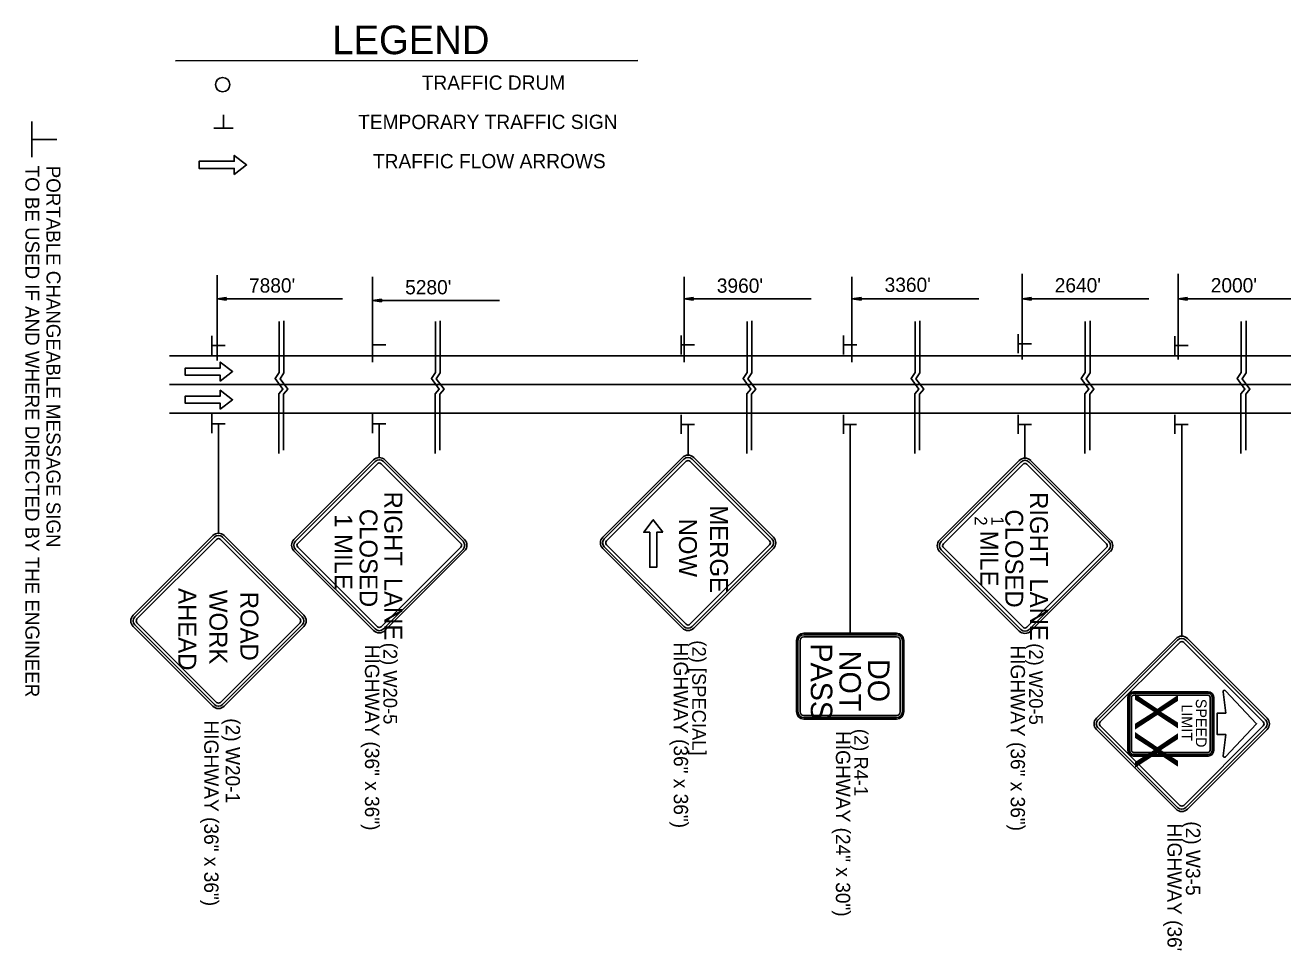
# Model space of a CAD drawing. Extents: x 1930579 to 1937521, y 596183 to 597566.
# Drawn here: x 1935128 to 1935656, y 596916 to 597301 of the extents above; entities that cross this region are included whole.
import ezdxf

# ---------------------------------------------------------------- set-up
doc = ezdxf.new("R2010")
doc.units = 0
for name, color, linetype in [('Default', 7, 'Continuous'), ('P_TC_Signs_Permanent', 7, 'Continuous'), ('P_TC_Signs_Temporary', 7, 'Continuous'), ('R_Annotation', 7, 'Continuous'), ('R_MOT', 7, 'Continuous'), ('R_Striping', 7, 'Continuous')]:
    doc.layers.add(name, color=color, linetype=linetype)

msp = doc.modelspace()

# ---------------------------------------------------------------- linework, layer by layer
at = {"layer": 'Default'}
for p, q in [((1935130.71, 597245.94), (1935130.71, 597260.96)), ((1935130.93, 597253.41), (1935141.18, 597253.41)), ((1935208.44, 597196.5), (1935208.44, 597160.58)), ((1935546.1, 597197.04), (1935546.1, 597161.13)), ((1935611.55, 597197.04), (1935611.55, 597161.13)), ((1935273.63, 597195.82), (1935273.63, 597159.91)), ((1935404.36, 597195.82), (1935404.36, 597159.91)), ((1935474.74, 597195.82), (1935474.74, 597159.91)), ((1935212.26, 597187.09), (1935208.44, 597186.51)), ((1935208.44, 597186.51), (1935261.07, 597186.51)), ((1935212.26, 597185.94), (1935208.44, 597186.51)), ((1935212.26, 597186.99), (1935209.08, 597186.51)), ((1935212.26, 597186.03), (1935209.08, 597186.51)), ((1935212.26, 597186.89), (1935209.73, 597186.51)), ((1935212.26, 597186.13), (1935209.73, 597186.51)), ((1935212.26, 597186.8), (1935210.37, 597186.51)), ((1935212.26, 597186.23), (1935210.37, 597186.51)), ((1935212.26, 597186.7), (1935211.02, 597186.51)), ((1935212.26, 597186.33), (1935211.02, 597186.51)), ((1935212.26, 597186.6), (1935211.66, 597186.51)), ((1935212.26, 597186.42), (1935211.66, 597186.51)), ((1935212.26, 597185.94), (1935212.26, 597187.09)), ((1935277.46, 597186.41), (1935273.63, 597185.83)), ((1935273.63, 597185.83), (1935326.86, 597185.83)), ((1935277.46, 597185.26), (1935273.63, 597185.83)), ((1935277.46, 597186.31), (1935274.27, 597185.83)), ((1935277.46, 597185.35), (1935274.27, 597185.83)), ((1935277.46, 597186.21), (1935274.93, 597185.83)), ((1935277.46, 597185.45), (1935274.93, 597185.83)), ((1935277.46, 597186.12), (1935275.57, 597185.83)), ((1935277.46, 597185.55), (1935275.57, 597185.83)), ((1935277.46, 597186.02), (1935276.21, 597185.83)), ((1935277.46, 597185.65), (1935276.21, 597185.83)), ((1935277.46, 597185.92), (1935276.85, 597185.83)), ((1935277.46, 597185.74), (1935276.85, 597185.83)), ((1935277.46, 597185.26), (1935277.46, 597186.41)), ((1935408.18, 597187.09), (1935404.36, 597186.51)), ((1935404.36, 597186.51), (1935457.59, 597186.51)), ((1935408.18, 597185.94), (1935404.36, 597186.51)), ((1935408.18, 597186.99), (1935405, 597186.51)), ((1935408.18, 597186.03), (1935405, 597186.51)), ((1935408.18, 597186.89), (1935405.65, 597186.51)), ((1935408.18, 597186.13), (1935405.65, 597186.51)), ((1935408.18, 597186.8), (1935406.29, 597186.51)), ((1935408.18, 597186.23), (1935406.29, 597186.51)), ((1935408.18, 597186.7), (1935406.94, 597186.51)), ((1935408.18, 597186.33), (1935406.94, 597186.51)), ((1935408.18, 597186.6), (1935407.58, 597186.51)), ((1935408.18, 597186.42), (1935407.58, 597186.51)), ((1935408.18, 597185.94), (1935408.18, 597187.09)), ((1935478.57, 597187.09), (1935474.74, 597186.51)), ((1935474.74, 597186.51), (1935527.97, 597186.51)), ((1935478.57, 597185.94), (1935474.74, 597186.51)), ((1935478.57, 597186.99), (1935475.38, 597186.51)), ((1935478.57, 597186.03), (1935475.38, 597186.51)), ((1935478.57, 597186.89), (1935476.04, 597186.51)), ((1935478.57, 597186.13), (1935476.04, 597186.51)), ((1935478.57, 597186.8), (1935476.67, 597186.51)), ((1935478.57, 597186.23), (1935476.67, 597186.51)), ((1935478.57, 597186.7), (1935477.32, 597186.51)), ((1935478.57, 597186.33), (1935477.32, 597186.51)), ((1935478.57, 597186.6), (1935477.96, 597186.51)), ((1935478.57, 597186.42), (1935477.96, 597186.51)), ((1935478.57, 597185.94), (1935478.57, 597187.09)), ((1935549.93, 597187.09), (1935546.1, 597186.51)), ((1935546.1, 597186.51), (1935599.33, 597186.51)), ((1935549.93, 597185.94), (1935546.1, 597186.51)), ((1935549.93, 597186.99), (1935546.74, 597186.51)), ((1935549.93, 597186.03), (1935546.74, 597186.51)), ((1935549.93, 597186.89), (1935547.4, 597186.51)), ((1935549.93, 597186.13), (1935547.4, 597186.51)), ((1935549.93, 597186.8), (1935548.04, 597186.51)), ((1935549.93, 597186.23), (1935548.04, 597186.51)), ((1935549.93, 597186.7), (1935548.69, 597186.51)), ((1935549.93, 597186.33), (1935548.69, 597186.51)), ((1935549.93, 597186.6), (1935549.32, 597186.51)), ((1935549.93, 597186.42), (1935549.32, 597186.51)), ((1935549.93, 597185.94), (1935549.93, 597187.09)), ((1935615.37, 597187.09), (1935611.55, 597186.51)), ((1935611.55, 597186.51), (1935664.78, 597186.51)), ((1935615.37, 597185.94), (1935611.55, 597186.51)), ((1935615.37, 597186.99), (1935612.18, 597186.51)), ((1935615.37, 597186.03), (1935612.18, 597186.51)), ((1935615.37, 597186.89), (1935612.84, 597186.51)), ((1935615.37, 597186.13), (1935612.84, 597186.51)), ((1935615.37, 597186.8), (1935613.48, 597186.51)), ((1935615.37, 597186.23), (1935613.48, 597186.51)), ((1935615.37, 597186.7), (1935614.13, 597186.51)), ((1935615.37, 597186.33), (1935614.13, 597186.51)), ((1935615.37, 597186.6), (1935614.77, 597186.51)), ((1935615.37, 597186.42), (1935614.77, 597186.51)), ((1935615.37, 597185.94), (1935615.37, 597187.09)), ((1935206.22, 597170.98), (1935206.22, 597163)), ((1935273.63, 597171.15), (1935273.63, 597163.17)), ((1935403.18, 597171.2), (1935403.18, 597163.22)), ((1935471.18, 597171.13), (1935471.18, 597163.15)), ((1935544.49, 597171.65), (1935544.49, 597163.68)), ((1935610.26, 597170.87), (1935610.26, 597162.89)), ((1935206.34, 597167.01), (1935211.78, 597167.01)), ((1935273.75, 597167.18), (1935279.2, 597167.18)), ((1935403.3, 597167.23), (1935408.75, 597167.23)), ((1935471.3, 597167.16), (1935476.75, 597167.16)), ((1935544.6, 597167.69), (1935550.05, 597167.69)), ((1935610.37, 597166.9), (1935615.82, 597166.9)), ((1936503.04, 597162.55), (1935188.53, 597162.55)), ((1936503.04, 597150.55), (1935188.53, 597150.55)), ((1936503.04, 597138.55), (1935188.53, 597138.55)), ((1935361.56, 597138.55), (1935431.95, 597138.55)), ((1935206.22, 597130.11), (1935206.22, 597138.09)), ((1935206.34, 597134.07), (1935211.78, 597134.07)), ((1935273.65, 597130.11), (1935273.65, 597138.09)), ((1935273.77, 597134.07), (1935279.21, 597134.07)), ((1935403.18, 597129.89), (1935403.18, 597137.87)), ((1935403.3, 597133.86), (1935408.75, 597133.86)), ((1935471.17, 597129.89), (1935471.17, 597137.87)), ((1935471.29, 597133.86), (1935476.73, 597133.86)), ((1935544.5, 597129.89), (1935544.5, 597137.87)), ((1935544.61, 597133.86), (1935550.06, 597133.86)), ((1935610.26, 597129.89), (1935610.26, 597137.87)), ((1935610.38, 597133.86), (1935615.83, 597133.86))]:
    msp.add_line(p, q, dxfattribs=at)
for points in [[(1935234.46, 597177.07), (1935234.46, 597155.55), (1935232.8, 597153.08), (1935236.04, 597148.65), (1935234.33, 597146.6), (1935234.33, 597121.58)], [(1935236.51, 597177.27), (1935236.51, 597155.46), (1935234.85, 597152.99), (1935238.08, 597148.56), (1935236.38, 597146.52), (1935236.38, 597123.02)], [(1935300.04, 597177.07), (1935300.04, 597155.55), (1935298.38, 597153.08), (1935301.62, 597148.65), (1935299.91, 597146.6), (1935299.91, 597121.58)], [(1935302.08, 597177.27), (1935302.08, 597155.46), (1935300.42, 597152.99), (1935303.66, 597148.56), (1935301.96, 597146.52), (1935301.95, 597123.02)], [(1935430.77, 597177.07), (1935430.77, 597155.55), (1935429.1, 597153.08), (1935432.34, 597148.65), (1935430.64, 597146.6), (1935430.63, 597121.58)], [(1935432.81, 597177.27), (1935432.81, 597155.46), (1935431.15, 597152.99), (1935434.39, 597148.56), (1935432.68, 597146.52), (1935432.68, 597123.02)], [(1935501.24, 597177.07), (1935501.24, 597155.55), (1935499.58, 597153.08), (1935502.81, 597148.65), (1935501.11, 597146.6), (1935501.1, 597121.58)], [(1935503.28, 597177.27), (1935503.28, 597155.46), (1935501.62, 597152.99), (1935504.86, 597148.56), (1935503.15, 597146.52), (1935503.15, 597123.02)], [(1935572.6, 597177.07), (1935572.6, 597155.55), (1935570.94, 597153.08), (1935574.18, 597148.65), (1935572.47, 597146.6), (1935572.47, 597121.58)], [(1935574.64, 597177.27), (1935574.64, 597155.46), (1935572.98, 597152.99), (1935576.22, 597148.56), (1935574.52, 597146.52), (1935574.51, 597123.02)], [(1935638.04, 597177.07), (1935638.04, 597155.55), (1935636.38, 597153.08), (1935639.62, 597148.65), (1935637.92, 597146.6), (1935637.91, 597121.58)], [(1935640.09, 597177.27), (1935640.09, 597155.46), (1935638.43, 597152.99), (1935641.66, 597148.56), (1935639.96, 597146.52), (1935639.96, 597123.02)]]:
    msp.add_lwpolyline(points, dxfattribs=at)
msp.add_circle((1935210.78, 597276.42), 3, dxfattribs=at)
at = {"layer": 'P_TC_Signs_Permanent'}
for p, q in [((1935493.51, 597046.19), (1935454.51, 597046.19)), ((1935493.51, 597045.59), (1935454.51, 597045.59)), ((1935493.51, 597044.69), (1935454.51, 597044.69)), ((1935610.72, 597043.97), (1935577.31, 597010.55)), ((1935648.9, 597010.55), (1935615.49, 597043.97)), ((1935451.51, 597043.19), (1935451.51, 597013.19)), ((1935452.11, 597043.19), (1935452.11, 597013.19)), ((1935453.01, 597043.19), (1935453.01, 597013.19)), ((1935495.01, 597013.19), (1935495.01, 597043.19)), ((1935495.91, 597013.19), (1935495.91, 597043.19)), ((1935496.51, 597013.19), (1935496.51, 597043.19)), ((1935611.38, 597043.3), (1935577.97, 597009.89)), ((1935612.31, 597042.37), (1935578.9, 597008.96)), ((1935647.31, 597008.96), (1935613.9, 597042.37)), ((1935648.24, 597009.89), (1935614.83, 597043.3)), ((1935590.51, 596997.07), (1935590.51, 597019.27)), ((1935592.91, 597021.67), (1935624.11, 597021.67)), ((1935626.51, 597019.27), (1935626.51, 596997.07)), ((1935454.51, 597011.69), (1935493.51, 597011.69)), ((1935454.51, 597010.79), (1935493.51, 597010.79)), ((1935454.51, 597010.19), (1935493.51, 597010.19)), ((1935577.97, 597006.44), (1935611.38, 596973.03)), ((1935578.9, 597007.37), (1935612.31, 596973.96)), ((1935613.9, 596973.96), (1935647.31, 597007.37)), ((1935614.83, 596973.03), (1935648.24, 597006.44)), ((1935577.31, 597005.78), (1935610.72, 596972.37)), ((1935615.49, 596972.37), (1935648.9, 597005.78)), ((1935624.11, 596994.67), (1935592.91, 596994.67))]:
    msp.add_line(p, q, dxfattribs=at)
for points in [[(1935591.11, 597019.27), (1935591.11, 596997.07)], [(1935592.01, 596997.07), (1935592.01, 597019.27)], [(1935624.11, 597021.07), (1935592.91, 597021.07)], [(1935592.91, 597020.17), (1935624.11, 597020.17)], [(1935625.01, 597019.27), (1935625.01, 597008.17), (1935625.01, 596997.07)], [(1935625.91, 596997.07), (1935625.91, 597008.17), (1935625.91, 597019.27)], [(1935630.46, 597021.63), (1935631.58, 597012.67), (1935628.01, 597012.67), (1935628.01, 597003.67), (1935631.57, 597003.67), (1935630.46, 596994.78)], [(1935631.42, 596994.32), (1935644.51, 597008.2), (1935631.42, 597022.08)], [(1935624.11, 596996.17), (1935592.91, 596996.17)], [(1935592.91, 596995.27), (1935624.11, 596995.27)]]:
    msp.add_lwpolyline(points, dxfattribs=at)
for centre, radius, start, end in [((1935454.51, 597043.19), 3, 90, 180), ((1935454.51, 597043.19), 2.4, 90, 180), ((1935454.51, 597043.19), 1.5, 90, 180), ((1935493.51, 597043.19), 3, 360, 90), ((1935493.51, 597043.19), 2.4, 360, 90), ((1935493.51, 597043.19), 1.5, 360, 90), ((1935613.1, 597041.58), 3.38, 45, 135), ((1935613.1, 597041.58), 2.44, 45, 135), ((1935613.1, 597041.58), 1.13, 45, 135), ((1935631.02, 597021.7), 0.563, 43.3117, 187.125), ((1935592.91, 597019.27), 2.4, 90, 180), ((1935592.91, 597019.27), 1.8, 90, 180), ((1935592.91, 597019.27), 0.9, 90, 180), ((1935624.11, 597019.27), 2.4, 0, 90), ((1935624.11, 597019.27), 1.8, 0, 90), ((1935624.11, 597019.27), 0.9, 0, 90), ((1935454.51, 597013.19), 3, 180, 270), ((1935454.51, 597013.19), 2.4, 180, 270), ((1935454.51, 597013.19), 1.5, 180, 270), ((1935493.51, 597013.19), 3, 270, 360), ((1935493.51, 597013.19), 2.4, 270, 360), ((1935493.51, 597013.19), 1.5, 270, 360), ((1935579.69, 597008.17), 3.38, 135, 225), ((1935579.69, 597008.17), 2.44, 135, 225), ((1935579.69, 597008.17), 1.13, 135, 225), ((1935646.51, 597008.17), 1.13, 315, 45), ((1935646.51, 597008.17), 2.44, 315, 45), ((1935646.51, 597008.17), 3.38, 315, 45), ((1935592.91, 596997.07), 2.4, 180, 270), ((1935592.91, 596997.07), 1.8, 180, 270), ((1935592.91, 596997.07), 0.9, 180, 270), ((1935624.11, 596997.07), 2.4, 270, 0), ((1935624.11, 596997.07), 1.8, 270, 0), ((1935624.11, 596997.07), 0.9, 270, 0), ((1935631.02, 596994.71), 0.563, 172.875, 316.6883), ((1935613.1, 596974.76), 3.38, 225, 315), ((1935613.1, 596974.76), 2.44, 225, 315), ((1935613.1, 596974.76), 1.13, 225, 315)]:
    msp.add_arc(centre, radius, start, end, dxfattribs=at)
at = {"layer": 'P_TC_Signs_Temporary'}
for p, q in [((1935240.69, 597085.51), (1935274.1, 597118.92)), ((1935241.36, 597084.85), (1935274.77, 597118.26)), ((1935242.29, 597083.92), (1935275.7, 597117.33)), ((1935277.29, 597117.33), (1935310.7, 597083.92)), ((1935278.21, 597118.26), (1935311.63, 597084.85)), ((1935278.88, 597118.92), (1935312.29, 597085.51)), ((1935370.23, 597086.53), (1935403.64, 597119.94)), ((1935370.89, 597085.87), (1935404.3, 597119.28)), ((1935371.82, 597084.94), (1935405.23, 597118.35)), ((1935406.82, 597118.35), (1935440.23, 597084.94)), ((1935407.75, 597119.28), (1935441.16, 597085.87)), ((1935408.41, 597119.94), (1935441.82, 597086.53)), ((1935511.54, 597085.29), (1935544.95, 597118.71)), ((1935512.2, 597084.63), (1935545.61, 597118.04)), ((1935549.06, 597118.04), (1935582.47, 597084.63)), ((1935549.72, 597118.71), (1935583.13, 597085.29)), ((1935513.13, 597083.7), (1935546.54, 597117.11)), ((1935548.13, 597117.11), (1935581.54, 597083.7)), ((1935173.26, 597053.77), (1935206.67, 597087.18)), ((1935173.93, 597053.11), (1935207.34, 597086.52)), ((1935174.85, 597052.18), (1935208.26, 597085.59)), ((1935209.86, 597085.59), (1935243.27, 597052.18)), ((1935210.78, 597086.52), (1935244.19, 597053.11)), ((1935211.45, 597087.18), (1935244.86, 597053.77)), ((1935274.1, 597047.33), (1935240.69, 597080.74)), ((1935274.77, 597047.99), (1935241.36, 597081.4)), ((1935275.7, 597048.92), (1935242.29, 597082.33)), ((1935310.7, 597082.33), (1935277.29, 597048.92)), ((1935311.63, 597081.4), (1935278.21, 597047.99)), ((1935312.29, 597080.74), (1935278.88, 597047.33)), ((1935403.64, 597048.35), (1935370.23, 597081.76)), ((1935404.3, 597049.01), (1935370.89, 597082.42)), ((1935405.23, 597049.94), (1935371.82, 597083.35)), ((1935440.23, 597083.35), (1935406.82, 597049.94)), ((1935441.16, 597082.42), (1935407.75, 597049.01)), ((1935441.82, 597081.76), (1935408.41, 597048.35)), ((1935544.95, 597047.11), (1935511.54, 597080.52)), ((1935545.61, 597047.77), (1935512.2, 597081.18)), ((1935546.54, 597048.7), (1935513.13, 597082.11)), ((1935581.54, 597082.11), (1935548.13, 597048.7)), ((1935582.47, 597081.18), (1935549.06, 597047.77)), ((1935583.13, 597080.52), (1935549.72, 597047.11)), ((1935206.67, 597015.58), (1935173.26, 597049)), ((1935207.34, 597016.25), (1935173.93, 597049.66)), ((1935208.26, 597017.18), (1935174.85, 597050.59)), ((1935243.27, 597050.59), (1935209.86, 597017.18)), ((1935244.19, 597049.66), (1935210.78, 597016.25)), ((1935244.86, 597049), (1935211.45, 597015.58))]:
    msp.add_line(p, q, dxfattribs=at)
for centre, radius, start, end in [((1935276.49, 597116.53), 3.37, 45, 135), ((1935276.49, 597116.53), 2.44, 45, 135), ((1935276.49, 597116.53), 1.12, 45, 135), ((1935406.02, 597117.56), 3.37, 45, 135), ((1935406.02, 597117.56), 2.44, 45, 135), ((1935406.02, 597117.56), 1.12, 45, 135), ((1935547.34, 597116.32), 3.37, 45, 135), ((1935547.34, 597116.32), 2.44, 45, 135), ((1935547.34, 597116.32), 1.12, 45, 135), ((1935209.06, 597084.79), 3.37, 45, 135), ((1935209.06, 597084.79), 2.44, 45, 135), ((1935209.06, 597084.79), 1.12, 45, 135), ((1935243.08, 597083.12), 3.37, 135, 225), ((1935309.9, 597083.12), 3.38, 315, 45), ((1935372.61, 597084.14), 3.37, 135, 225), ((1935372.61, 597084.14), 2.44, 135, 225), ((1935439.44, 597084.14), 2.44, 315, 45), ((1935439.44, 597084.14), 3.38, 315, 45), ((1935243.08, 597083.12), 2.44, 135, 225), ((1935243.08, 597083.12), 1.13, 135, 225), ((1935309.9, 597083.12), 1.13, 315, 45), ((1935309.9, 597083.12), 2.44, 315, 45), ((1935372.61, 597084.14), 1.13, 135, 225), ((1935439.44, 597084.14), 1.13, 315, 45), ((1935513.93, 597082.91), 3.37, 135, 225), ((1935513.93, 597082.91), 2.44, 135, 225), ((1935513.93, 597082.91), 1.13, 135, 225), ((1935580.75, 597082.91), 1.13, 315, 45), ((1935580.75, 597082.91), 2.44, 315, 45), ((1935580.75, 597082.91), 3.38, 315, 45), ((1935175.65, 597051.38), 3.37, 135, 225), ((1935175.65, 597051.38), 2.44, 135, 225), ((1935175.65, 597051.38), 1.13, 135, 225), ((1935242.47, 597051.38), 1.13, 315, 45), ((1935242.47, 597051.38), 2.44, 315, 45), ((1935242.47, 597051.38), 3.38, 315, 45), ((1935276.49, 597049.71), 1.12, 225, 315), ((1935406.02, 597050.73), 2.44, 225, 315), ((1935406.02, 597050.73), 1.12, 225, 315), ((1935547.34, 597049.5), 1.12, 225, 315), ((1935276.49, 597049.71), 3.38, 225, 315), ((1935276.49, 597049.71), 2.44, 225, 315), ((1935406.02, 597050.73), 3.38, 225, 315), ((1935547.34, 597049.5), 3.38, 225, 315), ((1935547.34, 597049.5), 2.44, 225, 315), ((1935209.06, 597017.97), 1.12, 225, 315), ((1935209.06, 597017.97), 3.38, 225, 315), ((1935209.06, 597017.97), 2.44, 225, 315)]:
    msp.add_arc(centre, radius, start, end, dxfattribs=at)
at = {"layer": 'R_Annotation'}
for p, q in [((1935191, 597286.46), (1935384.92, 597286.59)), ((1935211.16, 597258.26), (1935211.16, 597263.72)), ((1935215.14, 597258.14), (1935207.14, 597258.14)), ((1935209.06, 597134.08), (1935209.06, 597088.17)), ((1935209.06, 597134.07), (1935209.06, 597089.62)), ((1935276.49, 597134.07), (1935276.49, 597119.91)), ((1935406.02, 597133.86), (1935406.02, 597120.93)), ((1935474.01, 597133.86), (1935474.01, 597046.19)), ((1935547.34, 597133.86), (1935547.34, 597119.69)), ((1935613.1, 597133.86), (1935613.1, 597044.95))]:
    msp.add_line(p, q, dxfattribs=at)
at = {"layer": 'R_MOT'}
for points in [[(1935215.65, 597238.74), (1935220.84, 597242.75), (1935215.65, 597246.74), (1935215.65, 597244.24), (1935200.94, 597244.23), (1935200.94, 597241.23), (1935215.65, 597241.24)], [(1935395.41, 597088.6), (1935391.41, 597093.79), (1935387.41, 597088.6), (1935389.91, 597088.6), (1935389.91, 597073.89), (1935392.91, 597073.89), (1935392.91, 597088.6)]]:
    msp.add_lwpolyline(points, close=True, dxfattribs=at)
at = {"layer": 'R_Striping'}
for points in [[(1935209.8, 597151.97), (1935214.99, 597155.97), (1935209.8, 597159.97), (1935209.8, 597157.47), (1935195.09, 597157.47), (1935195.09, 597154.47), (1935209.8, 597154.47)], [(1935209.8, 597140.19), (1935214.99, 597144.19), (1935209.8, 597148.19), (1935209.8, 597145.69), (1935195.09, 597145.69), (1935195.09, 597142.69), (1935209.8, 597142.69)]]:
    msp.add_lwpolyline(points, close=True, dxfattribs=at)

# ---------------------------------------------------------------- texts
at = {"layer": 'Default'}
for s, height, rotation, p in [('TO BE USED IF AND WHERE DIRECTED BY THE ENGINEER', 5.8751, 270, (1935128.03, 597242.39)), ('PORTABLE CHANGEABLE MESSAGE SIGN', 5.8751, 270, (1935136.9, 597242.39)), ("7880'", 6, 360, (1935221.85, 597189.15)), ("5280'", 6, 360, (1935287.35, 597188.41)), ("3960'", 6, 360, (1935418.07, 597189.07)), ("3360'", 6, 360, (1935488.46, 597189.41)), ("2640'", 6, 360, (1935559.82, 597189.23)), ("2000'", 6, 360, (1935625.26, 597189.23))]:
    msp.add_text(s, height=height, rotation=rotation, dxfattribs=at).set_placement(p)
at = {"layer": 'P_TC_Signs_Permanent'}
for s, height, rotation, p in [('PASS', 9, 270, (1935457.51, 597041.9)), ('NOT', 9, 269.9596, (1935469.52, 597038.84)), ('DO', 9, 270, (1935481.51, 597035.36)), ('XX', 18, 270, (1935593.51, 597021.31)), ('SPEED', 4.5, 270, (1935619.01, 597018.67)), ('LIMIT', 4.5, 270, (1935613.01, 597016.36))]:
    msp.add_text(s, height=height, rotation=rotation, dxfattribs=at).set_placement(p)
at = {"layer": 'P_TC_Signs_Temporary'}
for s, height, p in [('RIGHT\u2002LANE', 7.5, (1935278.62, 597105.64)), ('RIGHT\u2002LANE', 7.5, (1935549.46, 597105.43)), ('CLOSED', 7.5, (1935268.24, 597098.38)), ('MERGE', 7.5, (1935415.24, 597099.9)), ('CLOSED', 7.5, (1935539.09, 597098.16)), ('1 MILE', 7.5, (1935257.74, 597096.17)), ('NOW', 7.5, (1935402.21, 597094.31)), ('2', 5.25, (1935526.21, 597095.26)), ('1', 5.25, (1935533.21, 597095.26)), (' MILE', 7.5, (1935528.59, 597092)), (' AHEAD ', 7.5, (1935192.23, 597067.92)), ('WORK', 7.5, (1935205.25, 597064.37)), (' ROAD ', 7.5, (1935218.27, 597066.4))]:
    msp.add_text(s, height=height, rotation=270, dxfattribs=at).set_placement(p)
at = {"layer": 'R_Annotation'}
for s, height, rotation, p in [('LEGEND', 12, 0.0388, (1935256.74, 597289.18)), ('TRAFFIC DRUM', 6, 0.0388, (1935294.32, 597274.23)), ('TEMPORARY TRAFFIC SIGN', 6, 0.0388, (1935267.65, 597257.74)), ('TRAFFIC FLOW ARROWS', 6, 0.0388, (1935273.85, 597241.28)), ('HIGHWAY (36" x 36")', 6, 270, (1935270.49, 597041.34)), ('(2) W20-5', 5.76, 270, (1935278.21, 597042.2)), ('HIGHWAY (36" x 36")', 6, 270, (1935400.02, 597042.36)), ('(2) [SPECIAL]', 5.76, 270, (1935407.75, 597043.22)), ('HIGHWAY (36" x 36")', 6, 270, (1935541.34, 597041.12)), ('(2) W20-5', 5.76, 270, (1935549.06, 597041.99)), ('HIGHWAY (36" x 36")', 6, 270, (1935203.06, 597009.6)), ('(2) W20-1', 6, 270, (1935212.05, 597010.51)), ('HIGHWAY (24" x 30")', 6, 270, (1935468.01, 597005.19)), ('(2) R4-1', 5.76, 270, (1935475.72, 597006.06)), ('HIGHWAY (36" x 36")', 6, 270, (1935607.1, 596966.38)), ('(2) W3-5', 6, 270, (1935614.83, 596967.28))]:
    msp.add_text(s, height=height, rotation=rotation, dxfattribs=at).set_placement(p)

doc.saveas('drawing.dxf')
